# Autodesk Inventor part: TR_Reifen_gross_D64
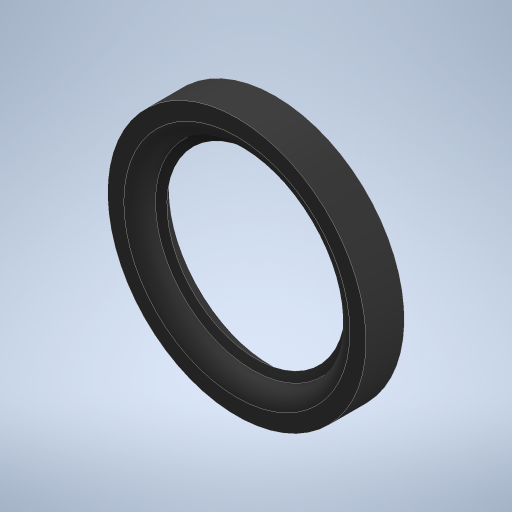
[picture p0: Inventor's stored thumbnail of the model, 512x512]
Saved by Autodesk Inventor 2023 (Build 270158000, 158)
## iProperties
Created: 2023-11
Part Number: TR_Reifen_gross_D64
Material: Gummi
Document SubType Name: Modeling
Designer: Administrator
Density: 0.93 g/cm^3
Appearance: Gummi - Schwarz
Author: Administrator
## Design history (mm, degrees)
sketch "Skizze1"
  geometry: L1 (32, 4.75)-(32, -4.75); L2 (32, -4.75)-(28, -4.75); L3 (24.078, -0.828)-(22.078, 0); L4 (22.078, 0)-(24.078, 0.828); L5 (28, 4.75)-(32, 4.75); L6 (24.078, 0.828)-(24.078, -0.828); L7 (0, -7.787)-(0, 7.787) reference; A1 r 3.922 centre (28, 0.828) between (28, 4.75) and (24.078, 0.828); A2 r 3.922 centre (28, -0.828) between (24.078, -0.828) and (28, -4.75); 2 further points
  constraints: 12 end point, 4 point on circle, 3 tangent, 2 centre point, 2 horizontal alignment, 2 vertical, 2 vertical alignment, 1 equal radius, 1 horizontal, 1 midpoint, 1 perpendicular
  dimensions: "d0" = 45 deg angle of L3 L4; "d1" = 9.5 distance of L1.start L1.end; "d2" = 32 horizontal distance of point (0, 0) L1.start; "d3" = 4 distance of L1.end L2.end; "d4" = 2 horizontal distance of L3.end L3.start
revolve "Umdrehung1" sketch "Skizze1" stored, may be unused: angle "d5" = 90 deg
node "Volumenkörper1"
